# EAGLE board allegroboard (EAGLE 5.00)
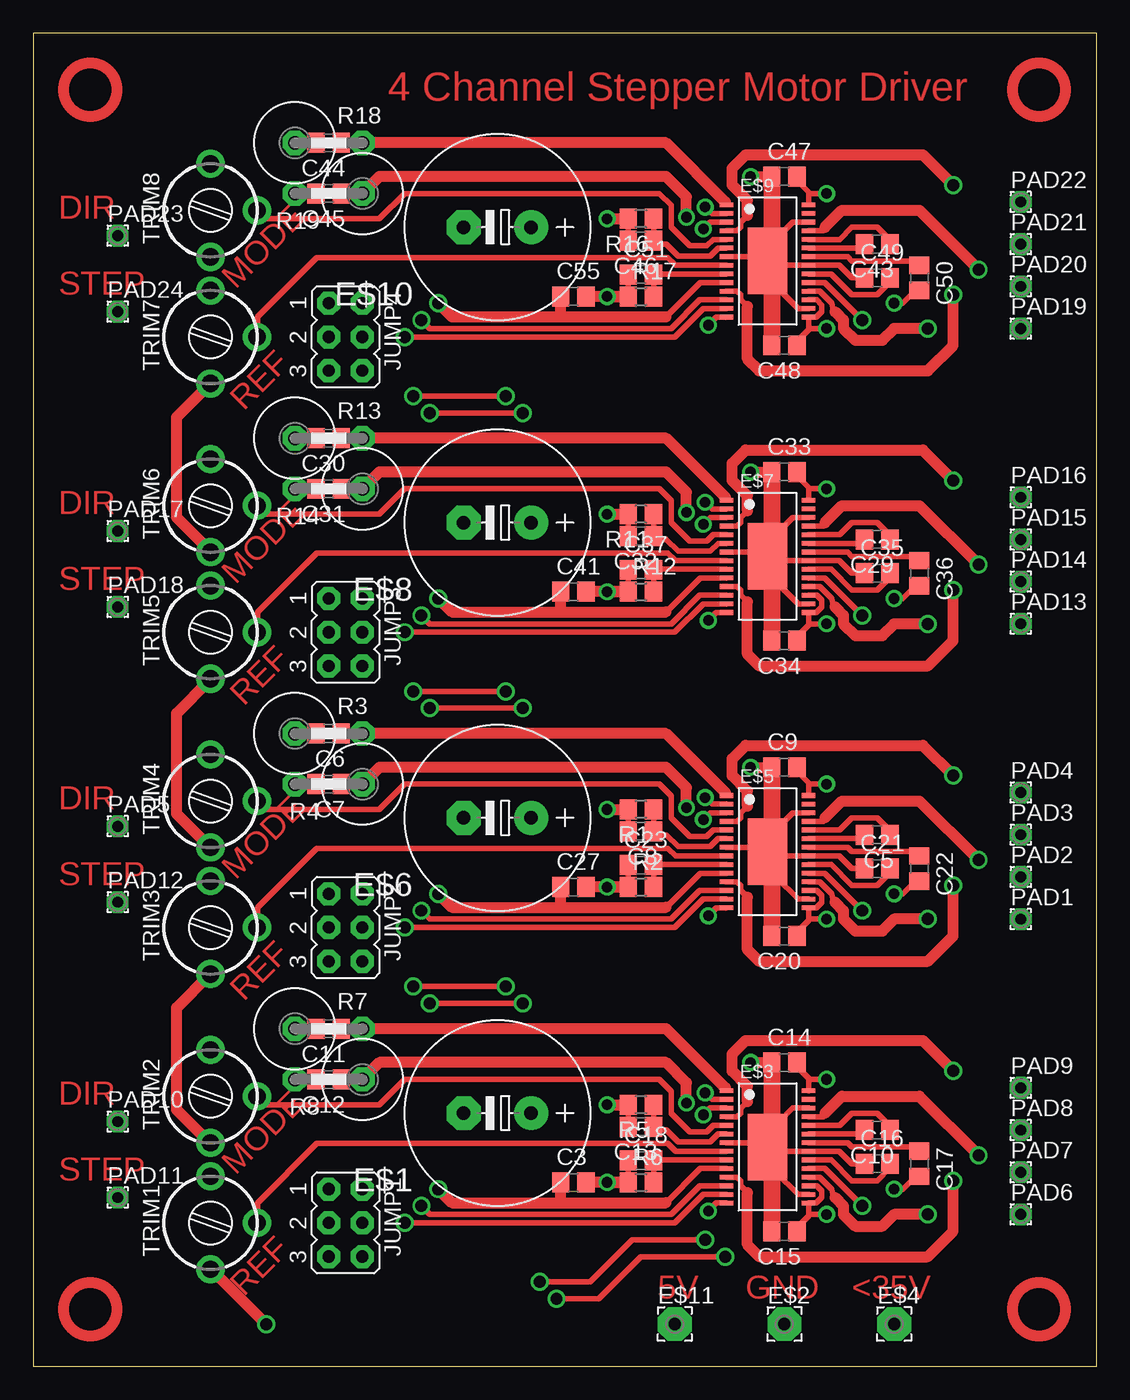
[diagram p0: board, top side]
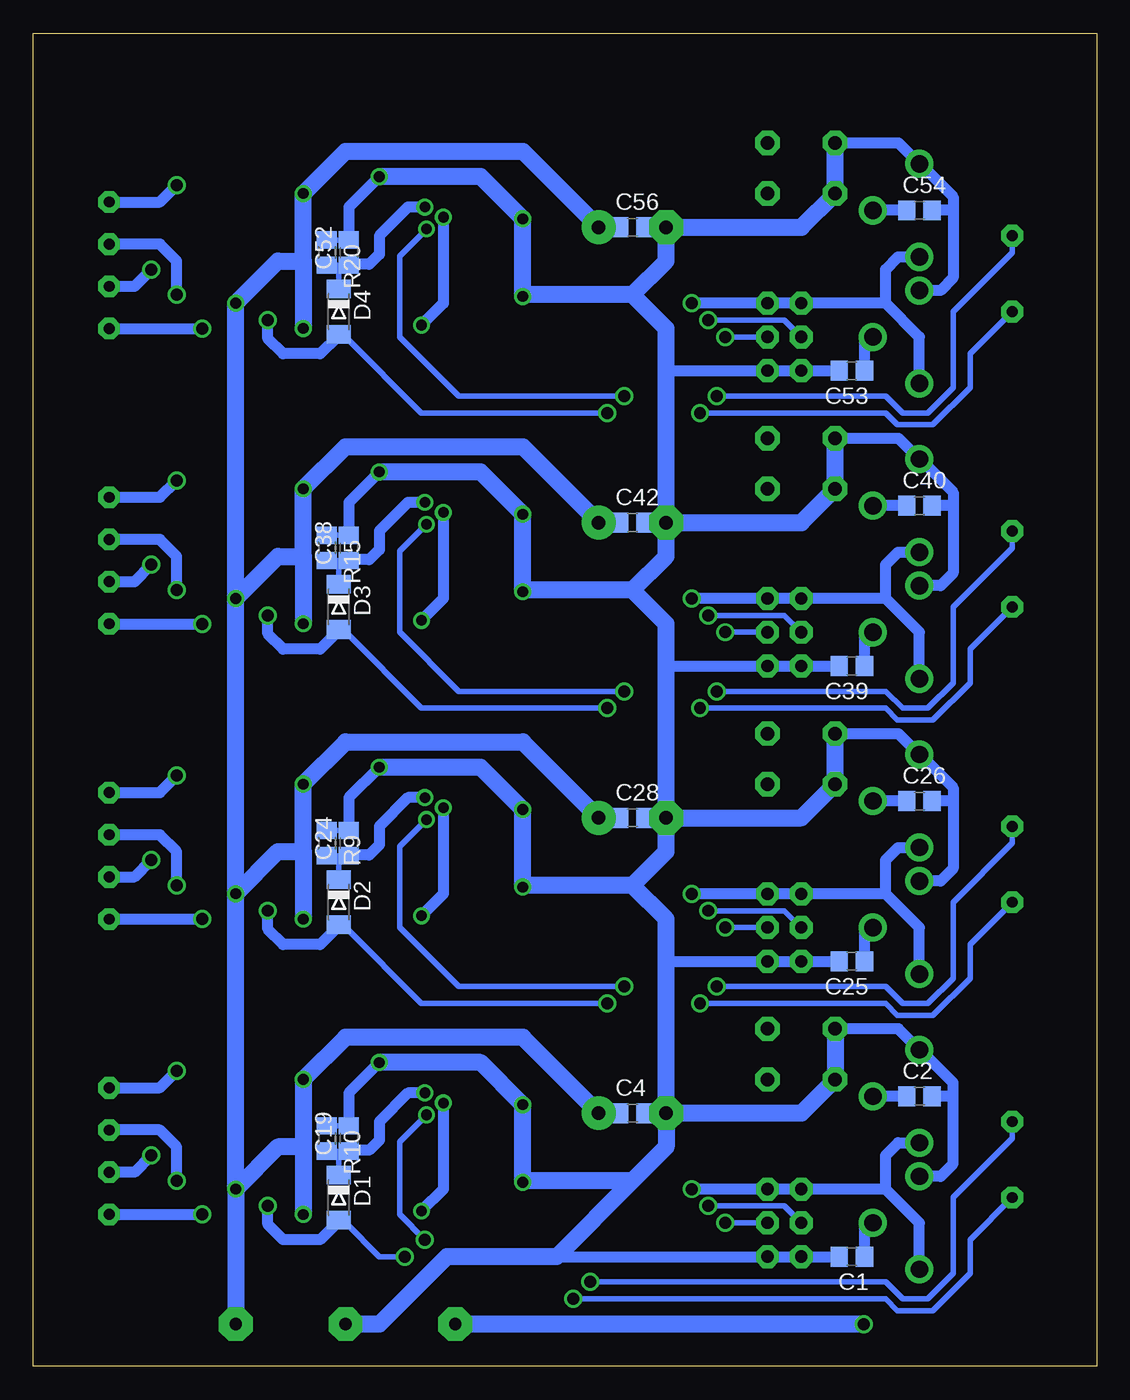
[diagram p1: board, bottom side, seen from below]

Size 80.01 x 100.33 mm. Coordinates in mm from the lower left corner, seen from the top.
Outline: 0,0 80.01,0 80.01,100.33 0,100.33 0,0
Copper layers (1*16): Top 0.035mm / dielectric 1.5mm / Bottom 0.035mm
Design rules "default *": minimum track width 10mil, minimum drill 24mil, track to track 8mil, track to pad 8mil, pad to pad 8mil, via to via 8mil, smd to smd 8mil, copper to edge 40mil, drill to drill 8mil, minimum pad ring 16mil, minimum via ring 8mil, stop-mask expansion 4mil, vias tented up to drill 0mil, thermal gap 10mil

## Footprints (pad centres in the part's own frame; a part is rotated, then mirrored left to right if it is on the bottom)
C0805 = smd 1.3 x 1.5: 1 -0.95,0; 2 0.95,0
MINIMELF = smd 1.4 x 1.8: A 1.7,0; C -1.7,0
E5-13 = drill 1.016 pad 2.54 round: + -2.54,0 | drill 1.016 pad 2.54 octagon: - 2.54,0
2,54/0,9 = drill 0.914 pad 2.54 octagon: 1 0,0
TSSOP28 = smd 0.35 x 1: 1 -4.225,-3.087; 2 -3.575,-3.087; 3 -2.925,-3.087; 4 -2.275,-3.087; 5 -1.625,-3.087; 6 -0.975,-3.087; 7 -0.325,-3.087; 8 0.325,-3.087; 9 0.975,-3.087; 10 1.625,-3.087; 11 2.275,-3.087; 12 2.925,-3.087; 13 3.575,-3.087; 14 4.225,-3.087; 15 4.225,3.087; 16 3.575,3.087; 17 2.925,3.087; 18 2.275,3.087; 19 1.625,3.087; 20 0.975,3.087; 21 0.325,3.087; 22 -0.325,3.087; 23 -0.975,3.087; 24 -1.625,3.087; 25 -2.275,3.087; 26 -2.925,3.087; 27 -3.575,3.087; 28 -4.225,3.087 | smd 5 x 3: EXP 0,0
JP3Q = drill 0.914 octagon: 1 -2.54,-1.27; 2 -2.54,1.27; 3 0,-1.27; 4 0,1.27; 5 2.54,-1.27; 6 2.54,1.27
1,6/0,8 = drill 0.813 pad 1.6 octagon: 1 0,0
R0805 = smd 1.3 x 1.5: 1 -0.95,0; 2 0.95,0
0617V = drill 1.016 octagon: 1 -2.54,0; 2 2.54,0
CTRIM3040.427 = drill 1.3 round: 1A -3.5,0; 1B 3.5,0; 2 0,-3.5

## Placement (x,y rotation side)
C1  100n  [C0805]  18.41,8.26 180 bottom
C2  100n  [C0805]  13.34,20.32 0 bottom
C3  100n  [C0805]  40.64,13.84 0 top
C4  100n  [C0805]  34.92,19.05 0 bottom
C5  220n  [C0805]  63.5,40.01 180 top
C6  100n  [C0805]  22.23,47.62 180 top
C7  100n  [C0805]  22.23,43.81 180 top
C8  1n  [C0805]  45.72,40.26 180 top
C9  100n  [C0805]  56.52,45.09 0 top
C10  220n  [C0805]  63.5,17.78 180 top
C11  100n  [C0805]  22.23,25.4 180 top
C12  100n  [C0805]  22.23,21.59 180 top
C13  1n  [C0805]  45.72,18.03 180 top
C14  100n  [C0805]  56.52,22.86 0 top
C15  100n  [C0805]  56.52,10.16 180 top
C16  220n  [C0805]  63.5,15.24 0 top
C17  220n  [C0805]  66.67,15.24 270 top
C18  1n  [C0805]  45.72,15.49 0 top
C19  100n  [C0805]  56.26,17.14 90 bottom
C20  100n  [C0805]  56.52,32.38 180 top
C21  220n  [C0805]  63.5,37.47 0 top
C22  220n  [C0805]  66.67,37.47 270 top
C23  1n  [C0805]  45.72,37.72 0 top
C24  100n  [C0805]  56.26,39.37 90 bottom
C25  100n  [C0805]  18.41,30.48 180 bottom
C26  100n  [C0805]  13.34,42.55 0 bottom
C27  100n  [C0805]  40.64,36.07 0 top
C28  100n  [C0805]  34.92,41.27 0 bottom
C29  220n  [C0805]  63.5,62.23 180 top
C30  100n  [C0805]  22.23,69.85 180 top
C31  100n  [C0805]  22.23,66.04 180 top
C32  1n  [C0805]  45.72,62.48 180 top
C33  100n  [C0805]  56.52,67.31 0 top
C34  100n  [C0805]  56.52,54.61 180 top
C35  220n  [C0805]  63.5,59.69 0 top
C36  220n  [C0805]  66.67,59.69 270 top
C37  1n  [C0805]  45.72,59.94 0 top
C38  100n  [C0805]  56.26,61.59 90 bottom
C39  100n  [C0805]  18.41,52.7 180 bottom
C40  100n  [C0805]  13.34,64.77 0 bottom
C41  100n  [C0805]  40.64,58.29 0 top
C42  100n  [C0805]  34.92,63.5 0 bottom
C43  220n  [C0805]  63.5,84.45 180 top
C44  100n  [C0805]  22.23,92.08 180 top
C45  100n  [C0805]  22.23,88.27 180 top
C46  1n  [C0805]  45.72,84.71 180 top
C47  100n  [C0805]  56.52,89.53 0 top
C48  100n  [C0805]  56.52,76.83 180 top
C49  220n  [C0805]  63.5,81.92 0 top
C50  220n  [C0805]  66.67,81.92 270 top
C51  1n  [C0805]  45.72,82.17 0 top
C52  100n  [C0805]  56.26,83.82 90 bottom
C53  100n  [C0805]  18.41,74.93 180 bottom
C54  100n  [C0805]  13.34,87 0 bottom
C55  100n  [C0805]  40.64,80.52 0 top
C56  100n  [C0805]  34.92,85.72 0 bottom
D1  [MINIMELF]  57.02,12.7 270 bottom
D2  [MINIMELF]  57.02,34.92 270 bottom
D3  [MINIMELF]  57.02,57.15 270 bottom
D4  [MINIMELF]  57.02,79.38 270 bottom
E$1  470µ  [E5-13]  34.92,19.05 180 top
E$2  [2,54/0,9]  56.52,3.17 0 top
E$3  [TSSOP28]  55.24,16.51 270 top
E$4  [2,54/0,9]  64.77,3.17 0 top
E$5  [TSSOP28]  55.24,38.73 270 top
E$6  470µ  [E5-13]  34.92,41.27 180 top
E$7  [TSSOP28]  55.24,60.96 270 top
E$8  470µ  [E5-13]  34.92,63.5 180 top
E$9  [TSSOP28]  55.24,83.19 270 top
E$10  470µ  [E5-13]  34.92,85.72 180 top
E$11  [2,54/0,9]  48.26,3.17 0 top
JUMP1  [JP3Q]  23.5,10.79 270 top
JUMP2  [JP3Q]  23.5,33.02 270 top
JUMP3  [JP3Q]  23.5,55.24 270 top
JUMP4  [JP3Q]  23.5,77.47 270 top
PAD1  [1,6/0,8]  74.3,33.66 0 top
PAD2  [1,6/0,8]  74.3,36.83 0 top
PAD3  [1,6/0,8]  74.3,40.01 0 top
PAD4  [1,6/0,8]  74.3,43.18 0 top
PAD5  [1,6/0,8]  6.35,40.64 0 top
PAD6  [1,6/0,8]  74.3,11.43 0 top
PAD7  [1,6/0,8]  74.3,14.61 0 top
PAD8  [1,6/0,8]  74.3,17.78 0 top
PAD9  [1,6/0,8]  74.3,20.95 0 top
PAD10  [1,6/0,8]  6.35,18.41 0 top
PAD11  [1,6/0,8]  6.35,12.7 0 top
PAD12  [1,6/0,8]  6.35,34.92 0 top
PAD13  [1,6/0,8]  74.3,55.88 0 top
PAD14  [1,6/0,8]  74.3,59.05 0 top
PAD15  [1,6/0,8]  74.3,62.23 0 top
PAD16  [1,6/0,8]  74.3,65.41 0 top
PAD17  [1,6/0,8]  6.35,62.87 0 top
PAD18  [1,6/0,8]  6.35,57.15 0 top
PAD19  [1,6/0,8]  74.3,78.11 0 top
PAD20  [1,6/0,8]  74.3,81.28 0 top
PAD21  [1,6/0,8]  74.3,84.45 0 top
PAD22  [1,6/0,8]  74.3,87.63 0 top
PAD23  [1,6/0,8]  6.35,85.09 0 top
PAD24  [1,6/0,8]  6.35,79.38 0 top
R1  30k  [R0805]  45.72,41.91 180 top
R2  30k  [R0805]  45.72,36.07 0 top
R3  0,22  [0617V]  22.23,47.62 0 top
R4  0,22  [0617V]  22.23,43.81 180 top
R5  30k  [R0805]  45.72,19.68 180 top
R6  30k  [R0805]  45.72,13.84 0 top
R7  0,22  [0617V]  22.23,25.4 0 top
R8  0,22  [0617V]  22.23,21.59 180 top
R9  10k  [R0805]  57.91,39.37 270 bottom
R10  10k  [R0805]  57.91,17.14 270 bottom
R11  30k  [R0805]  45.72,64.14 180 top
R12  30k  [R0805]  45.72,58.29 0 top
R13  0,22  [0617V]  22.23,69.85 0 top
R14  0,22  [0617V]  22.23,66.04 180 top
R15  10k  [R0805]  57.91,61.59 270 bottom
R16  30k  [R0805]  45.72,86.36 180 top
R17  30k  [R0805]  45.72,80.52 0 top
R18  0,22  [0617V]  22.23,92.08 0 top
R19  0,22  [0617V]  22.23,88.27 180 top
R20  10k  [R0805]  57.91,83.82 270 bottom
TRIM1  [CTRIM3040.427]  13.34,10.79 90 top
TRIM2  [CTRIM3040.427]  13.34,20.32 90 top
TRIM3  [CTRIM3040.427]  13.34,33.02 90 top
TRIM4  [CTRIM3040.427]  13.34,42.55 90 top
TRIM5  [CTRIM3040.427]  13.34,55.24 90 top
TRIM6  [CTRIM3040.427]  13.34,64.77 90 top
TRIM7  [CTRIM3040.427]  13.34,77.47 90 top
TRIM8  [CTRIM3040.427]  13.34,87 90 top

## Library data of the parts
C1-C56 = ref-packages
D1-D4 = diode
E$1 E$6 E$8 E$10 R1-R20 TRIM1-TRIM8 = rcl
E$2 E$4 E$11 PAD1-PAD24 = wirepad
E$3 E$5 E$7 E$9 = linear
JUMP1-JUMP4 = jumper

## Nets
GND1: C1.2 C2.2 C3.2 C4.2 C6.2 C7.2 C8.2 C9.1 C11.2 C12.2 C13.2 C14.1 C15.2 C16.1 C18.1 C19.2 C20.2 C21.1 C23.1 C24.2 C25.2 C26.2 C27.2 C28.2 C30.2 C31.2 C32.2 C33.1 C34.2 C35.1 C37.1 C38.2 C39.2 C40.2 C41.2 C42.2 C44.2 C45.2 C46.2 C47.1 C48.2 C49.1 C51.1 C52.2 C53.2 C54.2 C55.2 C56.2 E$1.- E$2.1 E$3.7 E$3.16 E$3.21 E$3.26 E$3.EXP E$5.7 E$5.16 E$5.21 E$5.26 E$5.EXP E$6.- E$7.7 E$7.16 E$7.21 E$7.26 E$7.EXP E$8.- E$9.7 E$9.16 E$9.21 E$9.26 E$9.EXP E$10.- JUMP1.5 JUMP1.6 JUMP2.5 JUMP2.6 JUMP3.5 JUMP3.6 JUMP4.5 JUMP4.6 R1.2 R2.1 R3.1 R4.2 R5.2 R6.1 R7.1 R8.2 R9.1 R10.1 R11.2 R12.1 R13.1 R14.2 R15.1 R16.2 R17.1 R18.1 R19.2 R20.1 TRIM1.1B TRIM2.1B TRIM3.1B TRIM4.1B TRIM5.1B TRIM6.1B TRIM7.1B TRIM8.1B
S$1: E$3.18 PAD6.1
S$2: C8.1 E$5.6 R1.1
S$3: C23.2 E$5.9 R2.2
S$4: C5.1 E$5.24
S$5: C5.2 E$5.23
S$6: C21.2 E$5.20
S$7: C22.1 E$5.22
S$8: E$5.25 PAD2.1
S$9: E$5.11 PAD3.1
S$10: E$5.4 PAD4.1
S$11: E$5.13 JUMP2.4
S$12: E$5.12 JUMP2.3
S$13: C25.1 E$5.8 TRIM3.2
S$14: C26.1 E$5.5 TRIM4.2
S$15: E$5.3 PAD5.1
S$16: C13.1 E$3.6 R5.1
S$17: C6.1 E$5.1 R3.2
S$18: C3.1 C27.1 C41.1 C55.1 E$3.10 E$5.10 E$7.10 E$9.10 E$11.1 JUMP1.1 JUMP1.2 JUMP2.1 JUMP2.2 JUMP3.1 JUMP3.2 JUMP4.1 JUMP4.2 TRIM1.1A TRIM2.1A TRIM3.1A TRIM4.1A TRIM5.1A TRIM6.1A TRIM7.1A TRIM8.1A
S$19: C18.2 E$3.9 R6.2
S$20: C10.1 E$3.24
S$21: C10.2 E$3.23
S$22: C1.1 E$3.8 TRIM1.2
S$23: C16.2 E$3.20
S$24: C17.1 E$3.22
S$25: E$3.25 PAD7.1
S$27: E$3.11 PAD8.1
S$28: E$3.4 PAD9.1
S$29: E$3.13 JUMP1.4
S$30: E$3.12 JUMP1.3
S$31: C24.1 D2.C E$5.2 R9.2
S$32: E$5.18 PAD1.1
S$33: C2.1 E$3.5 TRIM2.2
S$35: E$3.3 PAD10.1
S$36: D1.A E$3.19 PAD11.1
S$37: D2.A E$5.19 PAD12.1
S$38: C11.1 E$3.1 R7.2
S$39: C4.1 C9.2 C14.2 C15.1 C17.2 C20.1 C22.2 C28.1 C33.2 C34.1 C36.2 C42.1 C47.2 C48.1 C50.2 C56.1 E$1.+ E$3.15 E$3.17 E$3.28 E$4.1 E$5.15 E$5.17 E$5.28 E$6.+ E$7.15 E$7.17 E$7.28 E$8.+ E$9.15 E$9.17 E$9.28 E$10.+
S$40: C19.1 D1.C E$3.2 R10.2
S$41: C32.1 E$7.6 R11.1
S$42: C37.2 E$7.9 R12.2
S$43: C29.1 E$7.24
S$44: C29.2 E$7.23
S$45: C35.2 E$7.20
S$46: C36.1 E$7.22
S$47: E$7.25 PAD14.1
S$48: E$7.11 PAD15.1
S$49: E$7.4 PAD16.1
S$50: E$7.13 JUMP3.4
S$51: E$7.12 JUMP3.3
S$52: C39.1 E$7.8 TRIM5.2
S$53: C40.1 E$7.5 TRIM6.2
S$54: E$7.3 PAD17.1
S$55: C30.1 E$7.1 R13.2
S$57: C38.1 D3.C E$7.2 R15.2
S$58: E$7.18 PAD13.1
S$60: D3.A E$7.19 PAD18.1
S$61: C46.1 E$9.6 R16.1
S$62: C51.2 E$9.9 R17.2
S$63: C43.1 E$9.24
S$64: C43.2 E$9.23
S$65: C49.2 E$9.20
S$66: C50.1 E$9.22
S$67: E$9.25 PAD20.1
S$68: E$9.11 PAD21.1
S$69: E$9.4 PAD22.1
S$70: E$9.13 JUMP4.4
S$71: E$9.12 JUMP4.3
S$72: C53.1 E$9.8 TRIM7.2
S$73: C54.1 E$9.5 TRIM8.2
S$74: E$9.3 PAD23.1
S$75: C44.1 E$9.1 R18.2
S$77: C52.1 D4.C E$9.2 R20.2
S$78: E$9.18 PAD19.1
S$80: D4.A E$9.19 PAD24.1
SENSE1: C12.1 E$3.14 R8.1
SENSE2: C7.1 E$5.14 R4.1
SENSE3: C31.1 E$7.14 R14.1
SENSE4: C45.1 E$9.14 R19.1

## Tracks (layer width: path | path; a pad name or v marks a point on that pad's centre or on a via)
GND1  (via drill 0.8 pad 1.27)
  Top 0.305: E$3.26 58.26,19.43 | E$3.EXP 55.24,17.5 | E$5.26 58.26,41.66 | E$5.EXP 55.24,39.73 | E$7.26 58.26,63.88 | E$7.EXP 55.24,61.95 | E$9.26 58.26,86.11 | E$9.EXP 55.24,84.18
  Top 0.406: 62.57,15.54 62.87,15.24 C16.1 61.59,15.24 60.65,16.18 E$3.21 55.57,16.18 E$3.EXP | E$3.16 57.55,12.94 55.88,14.61 55.56,14.61 | E$3.26 57.15,19.43 56.13,18.41 56.13,17.4 E$3.EXP | E$3.7 54.92,16.84 E$3.EXP | C18.1 44.77,15.55 45.09,15.24 44.77,14.93 R6.1 | C13.2 44.77,18.1 44.83,18.16 44.77,18.22 R5.2 | 62.57,37.76 62.87,37.47 C21.1 61.59,37.47 60.65,38.41 E$5.21 55.57,38.41 E$5.EXP | E$5.16 57.55,35.16 55.88,36.83 55.56,36.83 | E$5.26 57.15,41.66 56.13,40.64 56.13,39.62 E$5.EXP | E$5.7 54.92,39.06 E$5.EXP | C23.1 44.77,37.78 45.09,37.47 44.77,37.15 R2.1 | C8.2 44.77,40.33 44.83,40.39 44.77,40.45 R1.2 | 62.57,59.98 62.87,59.69 C35.1 61.59,59.69 60.65,60.63 E$7.21 55.57,60.63 E$7.EXP | E$7.16 57.55,57.38 55.88,59.05 55.56,59.05 | E$7.26 57.15,63.88 56.13,62.87 56.13,61.85 E$7.EXP | E$7.7 54.92,61.28 E$7.EXP | C37.1 44.77,60.01 45.09,59.69 44.77,59.38 R12.1 | C32.2 44.77,62.55 44.83,62.61 44.77,62.67 R11.2 | 62.57,82.21 62.87,81.92 C49.1 61.59,81.92 60.65,82.86 E$9.21 55.57,82.86 E$9.EXP | E$9.16 57.55,79.61 55.88,81.28 55.56,81.28 | E$9.26 57.15,86.11 56.13,85.09 56.13,84.07 E$9.EXP | E$9.7 54.92,83.51 E$9.EXP | C51.1 44.77,82.23 45.09,81.92 44.77,81.6 R17.1 | C46.2 44.77,84.78 44.83,84.84 44.77,84.9 R16.2
  Top 0.813: 55.56,14.61 55.56,16.19 E$3.EXP 55.56,16.83 | C3.2 41.59,13.9 41.53,13.84 R6.1 v43.18,13.84 | v53.98,22.86 C14.1 | 19.68,25.09 R7.1 C11.2 21.59,25.4 | R8.2 C12.2 | 55.56,36.83 55.56,38.41 E$5.EXP 55.56,39.05 | C27.2 41.59,36.13 41.53,36.07 R2.1 v43.18,36.07 | v53.98,45.09 C9.1 | 19.68,47.31 R3.1 C6.2 21.59,47.62 | R4.2 C7.2 | 55.56,59.05 55.56,60.64 E$7.EXP 55.56,61.28 | C41.2 41.59,58.35 41.53,58.29 R12.1 v43.18,58.29 | v53.98,67.31 C33.1 | 19.68,69.53 R13.1 C30.2 21.59,69.85 | R14.2 C31.2 | 55.56,81.28 55.56,82.86 E$9.EXP 55.56,83.5 | C55.2 41.59,80.58 41.53,80.52 R17.1 v43.18,80.52 | v53.98,89.53 C47.1 | 19.68,91.76 R18.1 C44.2 21.59,92.08 | R19.2 C45.2 | v43.18,19.68 R5.2 v43.18,19.68 | v43.18,41.91 R1.2 v43.18,41.91 | v43.18,64.14 R11.2 v43.18,64.14 | v43.18,86.36 R16.2 v43.18,86.36
  Top 1.27: 55.56,14.61 C15.2 | C14.1 55.56,16.83 | 55.56,36.83 C20.2 | C9.1 55.56,39.05 | 55.56,59.05 C34.2 | C33.1 55.56,61.28 | 55.56,81.28 C48.2 | C47.1 55.56,83.5
  Bottom 0.406: R10.1 57.91,17.91 57.78,17.78 57.47,18.09 C19.2 | R9.1 57.91,40.13 57.78,40.01 57.47,40.32 C24.2 | R15.1 57.91,62.36 57.78,62.23 57.47,62.55 C38.2 | R20.1 57.91,84.58 57.78,84.45 57.47,84.77 C52.2
  Bottom 0.813: C19.2 56.26,20.57 v53.98,22.86 | 43.18,13.97 v43.18,13.84 | C1.2 JUMP1.5 JUMP1.6 40.64,8.26 | TRIM1.1B 11.74,14.29 10.79,15.24 10.79,20.32 | 10.79,20.32 10.79,21.34 13.03,23.57 TRIM2.1B 14.91,25.4 R7.1 | 10.79,20.32 C2.2 | E$1.- C4.2 | C24.2 56.26,42.8 v53.98,45.09 | 43.18,36.2 v43.18,36.07 | C25.2 JUMP2.5 JUMP2.6 32.38,30.48 | TRIM3.1B 11.74,36.52 10.79,37.47 10.79,42.55 | 10.79,42.55 10.79,43.56 13.03,45.79 TRIM4.1B 14.91,47.62 R3.1 | 10.79,42.55 C26.2 | E$6.- C28.2 | C38.2 56.26,65.02 v53.98,67.31 | 43.18,58.42 v43.18,58.29 | C39.2 JUMP3.5 JUMP3.6 32.38,52.7 | TRIM5.1B 11.74,58.74 10.79,59.69 10.79,64.77 | 10.79,64.77 10.79,65.79 13.03,68.02 TRIM6.1B 14.91,69.85 R13.1 | 10.79,64.77 C40.2 | E$8.- C42.2 | C52.2 56.26,87.25 v53.98,89.53 | 43.18,80.64 v43.18,80.52 | C53.2 JUMP4.5 JUMP4.6 32.38,74.93 | TRIM7.1B 11.74,80.97 10.79,81.92 10.79,87 | 10.79,87 10.79,88.01 13.03,90.24 TRIM8.1B 14.91,92.08 R18.1 | 10.79,87 C54.2 | E$10.- C56.2
  Bottom 1.27: v53.98,22.86 46.35,22.86 v43.18,19.68 43.18,13.97 34.92,13.97 | R7.1 R8.2 22.23,19.05 E$1.- | E$1.- 32.38,16.51 34.92,13.97 | v53.98,45.09 46.35,45.09 v43.18,41.91 43.18,36.2 34.92,36.2 | R3.1 R4.2 22.23,41.27 E$6.- | E$6.- 32.38,38.73 34.92,36.2 | v53.98,67.31 46.35,67.31 v43.18,64.14 43.18,58.42 34.92,58.42 | R13.1 R14.2 22.23,63.5 E$8.- | E$8.- 32.38,60.96 34.92,58.42 | v53.98,89.53 46.35,89.53 v43.18,86.36 43.18,80.64 34.92,80.64 | R18.1 R19.2 22.23,85.72 E$10.- 32.38,83.19 34.92,80.64 | E$2.1 53.98,3.17 48.9,8.26 40.64,8.26 34.92,13.97 | E$6.- 32.38,52.7 32.38,55.88 34.92,58.42 | E$8.- 32.38,74.93 32.38,78.11 34.92,80.64 | E$1.- 32.38,30.48 32.38,33.66 34.92,36.2
S$1  (via drill 0.9 pad 0.41)
  Top 0.406: E$3.18 59.17,14.23 60.07,13.34 60.2,12.83 60.33,12.7
  Top 0.813: 60.33,12.7 60.96,12.06 60.96,11.43 61.85,10.54 63.88,10.54 64.77,11.43 v67.31,11.43
  Bottom 0.813: PAD6.1 v67.31,11.43
S$2
  Top 0.406: R1.1 46.67,40.32 46.61,40.26 | C8.1 46.48,40.26 46.35,40.39 46.35,40.01 | 46.35,40.01 46.35,39.75 | 46.61,40.26 46.35,40.01 | C8.1 46.61,40.26 | 46.35,40.01 46.65,39.71 | E$5.6 51.52,39.71 50.93,39.12 48.51,39.12 47.62,40.01 46.99,40.01 46.74,40.26 C8.1
S$3
  Top 0.406: R2.2 46.67,37.4 46.61,37.47 46.67,37.53 C23.2 46.61,37.85 | 46.61,37.85 46.35,38.1 | E$5.9 46.7,37.76 46.61,37.85
S$4
  Top 0.406: E$5.24 60.68,40.36 61.59,41.27 63.5,41.27 64.45,40.33 C5.1
S$5
  Top 0.406: C5.2 62.87,40.01 62.57,39.71 E$5.23
S$6
  Top 0.406: E$5.20 60.03,37.76 61.59,36.2 63.5,36.2 64.45,37.15 C21.2
S$7
  Top 0.406: E$5.22 61.27,39.06 61.59,38.73 66.67,38.73 C22.1
S$8  (via drill 0.9 pad 0.41)
  Top 0.406: E$5.25 59.42,41.01 59.56,41.27
  Top 0.813: 59.56,41.27 60.83,42.55 66.67,42.55 v71.12,38.1
  Bottom 0.813: PAD2.1 72.39,36.83 v71.12,38.1
S$9  (via drill 0.9 pad 0.41)
  Top 0.406: E$5.11 52.95,36.46 53.21,36.2 53.21,35.81 53.72,35.31
  Top 0.813: 53.72,35.31 53.72,31.37 54.61,30.48 67.31,30.48 69.22,32.38 v69.22,36.2
  Bottom 0.813: PAD3.1 70.48,40.01 69.22,38.73 v69.22,36.2
S$10  (via drill 0.9 pad 0.41)
  Top 0.406: E$5.4 52.95,41.01 53.21,41.27 53.21,41.66 53.72,42.16
  Top 0.813: 53.72,42.16 53.72,43.31 52.58,44.45 52.58,45.72 53.59,46.74 66.93,46.74 v69.22,44.45
  Bottom 0.813: PAD4.1 70.48,43.18 v69.22,44.45
S$11  (via drill 0.9 pad 0.41)
  Top 0.406: E$5.13 50.4,35.16 48.26,33.02 v27.94,33.02
  Bottom 0.406: JUMP2.4 v27.94,33.02
S$12  (via drill 0.9 pad 0.41)
  Top 0.406: E$5.12 50.16,35.81 48.01,33.66 29.84,33.66 v29.21,34.29
  Bottom 0.406: JUMP2.3 23.5,34.29 v29.21,34.29
S$13
  Top 0.406: E$5.8 48.33,38.41 47.75,38.99 21.34,38.99 16.89,34.54 16.89,33.4 16.51,33.02 TRIM3.2
  Bottom 0.813: TRIM3.2 17.14,33.02 17.46,32.7 C25.1
S$14
  Top 0.406: 48.64,40.64 48.01,41.27 48.01,42.93 47.12,43.81 27.94,43.81 26.04,41.91 17.4,41.91 16.76,42.55 TRIM4.2 | 48.64,40.64 48.92,40.36 | E$5.5 51.16,40.36 50.67,39.88 49.4,39.88 48.64,40.64
  Bottom 0.813: C26.1 TRIM4.2
S$15  (via drill 0.8 pad 1.27, 0.9 pad 0.41)
  Top 0.406: E$5.3 50.93,41.66 v50.42,41.15 | v28.57,28.57 v35.56,28.57
  Bottom 0.406: v50.42,41.15 52.45,39.12 52.45,33.02 48.01,28.57 v35.56,28.57 | v28.57,28.57 15.88,28.57 14.61,27.3 12.7,27.3 10.79,29.21 10.79,34.92 6.35,39.37 PAD5.1
S$16
  Top 0.406: R5.1 46.67,18.09 46.61,18.03 | C13.1 46.48,18.03 46.35,18.16 46.35,17.78 | 46.35,17.78 46.35,17.53 | 46.61,18.03 46.35,17.78 | C13.1 46.61,18.03 | 46.35,17.78 46.65,17.48 | E$3.6 51.52,17.48 50.93,16.89 48.51,16.89 47.62,17.78 46.99,17.78 46.74,18.03 C13.1
S$17
  Top 0.305: E$5.1 52.16,43.09 52.07,43.18
  Top 0.813: 22.86,47.62 C6.1 R3.2 47.62,47.62 52.07,43.18
S$18  (via drill 0.9 pad 0.41)
  Top 0.406: E$3.10 50.19,14.88 47.62,12.32 | E$5.10 50.19,37.11 47.62,34.54 | E$7.10 50.19,59.34 47.62,56.77 | E$9.10 50.19,81.56 47.62,78.99
  Top 0.813: 39.75,12.32 31.5,12.32 v30.48,13.34 | 39.75,12.32 47.62,12.32 | C3.1 39.69,12.38 39.75,12.32 | 39.75,34.54 31.5,34.54 v30.48,35.56 | 39.75,34.54 47.62,34.54 | C27.1 39.69,34.6 39.75,34.54 | 39.75,56.77 31.5,56.77 v30.48,57.78 | 39.75,56.77 47.62,56.77 | C41.1 39.69,56.83 39.75,56.77 | 39.75,78.99 31.5,78.99 v30.48,80.01 | 39.75,78.99 47.62,78.99 | C55.1 39.69,79.06 39.75,78.99 | TRIM3.1A 10.79,26.98 10.79,19.3 13.34,16.76 TRIM2.1A | TRIM4.1A 10.79,41.59 10.79,49.15 13.34,51.69 TRIM5.1A | TRIM7.1A 10.79,71.43 10.79,63.88 13.34,61.34 TRIM6.1A | TRIM1.1A 13.41,7.29 v17.53,3.17
  Bottom 0.813: TRIM2.1A 14.93,16.82 15.88,15.88 15.88,13.34 | v30.48,13.34 JUMP1.2 JUMP1.1 15.88,13.34 | 15.88,13.34 13.34,10.79 TRIM1.1A | TRIM4.1A 14.93,39.05 15.88,38.1 15.88,35.56 | v30.48,35.56 JUMP2.2 JUMP2.1 15.88,35.56 | 15.88,35.56 13.34,33.02 TRIM3.1A | TRIM6.1A 14.93,61.27 15.88,60.33 15.88,57.78 | v30.48,57.78 JUMP3.2 JUMP3.1 15.88,57.78 | 15.88,57.78 13.34,55.24 TRIM5.1A | TRIM8.1A 14.93,83.5 15.88,82.55 15.88,80.01 | v30.48,80.01 JUMP4.2 JUMP4.1 15.88,80.01 | 15.88,80.01 13.34,77.47 TRIM7.1A
  Bottom 1.27: v17.53,3.17 E$11.1
S$19
  Top 0.406: R6.2 46.67,15.18 46.61,15.24 46.67,15.3 C18.2 46.61,15.62 | 46.61,15.62 46.35,15.88 | E$3.9 46.7,15.54 46.61,15.62
S$20
  Top 0.406: E$3.24 60.68,18.14 61.59,19.05 63.5,19.05 64.45,18.1 C10.1
S$21
  Top 0.406: C10.2 62.87,17.78 62.57,17.48 E$3.23
S$22
  Top 0.406: E$3.8 48.33,16.18 47.75,16.76 21.34,16.76 16.89,12.32 16.89,11.18 16.51,10.79 TRIM1.2
  Bottom 0.813: TRIM1.2 17.14,10.79 17.46,10.47 C1.1
S$23
  Top 0.406: E$3.20 60.03,15.54 61.59,13.97 63.5,13.97 64.45,14.92 C16.2
S$24
  Top 0.406: E$3.22 61.27,16.84 61.59,16.51 66.67,16.51 C17.1
S$25  (via drill 0.9 pad 0.41)
  Top 0.406: E$3.25 59.42,18.79 59.56,19.05
  Top 0.813: 59.56,19.05 60.83,20.32 66.67,20.32 v71.12,15.88
  Bottom 0.813: PAD7.1 72.39,14.61 v71.12,15.88
S$27  (via drill 0.9 pad 0.41)
  Top 0.406: E$3.11 52.95,14.23 53.21,13.97 53.21,13.59 53.72,13.08
  Top 0.813: 53.72,13.08 53.72,9.14 54.61,8.26 67.31,8.26 69.22,10.16 v69.22,13.97
  Bottom 0.813: PAD8.1 70.48,17.78 69.22,16.51 v69.22,13.97
S$28  (via drill 0.9 pad 0.41)
  Top 0.406: E$3.4 52.95,18.79 53.21,19.05 53.21,19.43 53.72,19.94
  Top 0.813: 53.72,19.94 53.72,21.08 52.58,22.23 52.58,23.5 53.59,24.51 66.93,24.51 v69.22,22.23
  Bottom 0.813: PAD9.1 70.48,20.95 v69.22,22.23
S$29  (via drill 0.9 pad 0.41)
  Top 0.406: E$3.13 50.4,12.94 48.26,10.79 v27.94,10.79
  Bottom 0.406: JUMP1.4 v27.94,10.79
S$30  (via drill 0.9 pad 0.41)
  Top 0.406: E$3.12 50.16,13.59 48.01,11.43 29.84,11.43 v29.21,12.06
  Bottom 0.406: JUMP1.3 23.5,12.06 v29.21,12.06
S$31  (via drill 0.8 pad 1.27)
  Top 0.406: E$5.2 51.07,42.31 v50.55,42.8
  Bottom 0.406: R9.2 57.91,38.23 57.78,38.1 57.47,38.42 57.15,38.42 | 57.15,38.42 C24.1 | 57.15,38.42 57.15,38.1 57.02,37.97 D2.C
  Bottom 0.813: v50.55,42.8 51.82,42.8 53.98,40.64 53.98,39.24 54.74,38.48 56.13,38.48 56.26,38.35 C24.1
S$32  (via drill 0.9 pad 0.41)
  Top 0.406: E$5.18 59.17,36.46 60.07,35.56 60.2,35.05 60.33,34.92
  Top 0.813: 60.33,34.92 60.96,34.29 60.96,33.66 61.85,32.77 63.88,32.77 64.77,33.66 v67.31,33.66
  Bottom 0.813: PAD1.1 v67.31,33.66
S$33
  Top 0.406: 48.64,18.41 48.01,19.05 48.01,20.7 47.12,21.59 27.94,21.59 26.04,19.68 17.4,19.68 16.76,20.32 TRIM2.2 | 48.64,18.41 48.92,18.14 | E$3.5 51.16,18.14 50.67,17.65 49.4,17.65 48.64,18.41
  Bottom 0.813: C2.1 TRIM2.2
S$35  (via drill 0.8 pad 1.27, 0.9 pad 0.41)
  Top 0.406: E$3.3 50.93,19.43 v50.42,18.92 | v50.55,9.53 45.09,9.53 41.91,6.35 v38.1,6.35
  Bottom 0.406: v50.42,18.92 52.45,16.89 52.45,11.43 v50.55,9.53 | v38.1,6.35 15.88,6.35 14.61,5.08 12.7,5.08 10.79,6.99 10.79,12.7 6.35,17.14 PAD10.1
S$36  (via drill 0.9, 0.9 pad 0.41)
  Top 0.406: E$3.19 59.54,14.88 v62.36,12.06 | v52.07,8.26 45.72,8.26 42.55,5.08 v39.37,5.08
  Bottom 0.406: 57.15,10.79 56.52,10.79 53.98,8.26 v52.07,8.26 | v39.37,5.08 15.88,5.08 14.99,4.19 12.32,4.19 9.53,6.99 9.53,9.53 PAD11.1
  Bottom 0.813: D1.A 57.02,10.92 57.15,10.79 58.42,9.53 61.21,9.53 62.36,10.67 v62.36,12.06
S$37  (via drill 0.9, 0.9 pad 0.41)
  Top 0.406: E$5.19 59.54,37.11 v62.36,34.29 | v29.84,27.3 v36.83,27.3
  Bottom 0.406: 57.15,33.02 56.52,33.02 50.8,27.3 v36.83,27.3 | v29.84,27.3 15.88,27.3 14.99,26.42 12.32,26.42 9.53,29.21 9.53,31.75 PAD12.1
  Bottom 0.813: D2.A 57.02,33.15 57.15,33.02 58.42,31.75 61.21,31.75 62.36,32.89 v62.36,34.29
S$38
  Top 0.305: E$3.1 52.16,20.87 52.07,20.95
  Top 0.813: 22.86,25.4 C11.1 R7.2 47.62,25.4 52.07,20.95
S$39  (via drill 0.8 pad 1.27)
  Top 0.406: C14.2 57.15,22.86 58.33,21.68 E$3.28 58.33,21.5 58.42,21.59 v59.69,21.59 | C17.2 66.67,14.61 65.41,13.34 v64.77,13.34 | E$3.17 58.93,13.59 59.31,13.21 59.31,12.7 58.89,12.29 E$3.15 58.33,11.43 | v59.69,11.43 58.33,11.43 | 58.33,11.43 58.33,11.34 58.29,11.3 | 58.29,11.3 57.47,10.47 C15.1 57.15,10.16 58.29,11.3 | C9.2 57.15,45.09 58.33,43.9 E$5.28 58.33,43.73 58.42,43.81 v59.69,43.81 | C22.2 66.67,36.83 65.41,35.56 v64.77,35.56 | E$5.17 58.93,35.81 59.31,35.43 59.31,34.92 58.89,34.51 E$5.15 58.33,33.66 | v59.69,33.66 58.33,33.66 | 58.33,33.66 58.33,33.57 58.29,33.53 | 58.29,33.53 57.47,32.7 C20.1 57.15,32.38 58.29,33.53 | C33.2 57.15,67.31 58.33,66.13 E$7.28 58.33,65.95 58.42,66.04 v59.69,66.04 | C36.2 66.67,59.05 65.41,57.78 v64.77,57.78 | E$7.17 58.93,58.03 59.31,57.66 59.31,57.15 58.89,56.73 E$7.15 58.33,55.88 | v59.69,55.88 58.33,55.88 | 58.33,55.88 58.33,55.79 58.29,55.75 | 58.29,55.75 57.47,54.92 C34.1 57.15,54.61 58.29,55.75 | C47.2 57.15,89.53 58.33,88.35 E$9.28 58.33,88.18 58.42,88.27 v59.69,88.27 | C50.2 66.67,81.28 65.41,80.01 v64.77,80.01 | E$9.17 58.93,80.26 59.31,79.88 59.31,79.38 58.89,78.96 E$9.15 58.33,78.11 | v59.69,78.11 58.33,78.11 | 58.33,78.11 58.33,78.02 58.29,77.98 | 58.29,77.98 57.47,77.15 C48.1 57.15,76.83 58.29,77.98
  Bottom 0.813: C4.1 E$1.+ | E$6.+ C28.1 | E$8.+ C42.1 | E$10.+ C56.1
  Bottom 1.27: 59.69,16.51 v59.69,21.59 56.52,24.77 43.18,24.77 E$1.+ | 59.69,16.51 v59.69,11.43 | v64.77,13.34 E$4.1 | 59.69,38.73 v59.69,43.81 56.52,46.99 43.18,46.99 E$6.+ | 59.69,38.73 v59.69,33.66 | v64.77,13.34 v64.77,35.56 | 59.69,60.96 v59.69,66.04 56.52,69.22 43.18,69.22 E$8.+ | 59.69,60.96 v59.69,55.88 | v64.77,35.56 v64.77,57.78 | 59.69,83.19 v59.69,88.27 56.52,91.44 43.18,91.44 E$10.+ | 59.69,83.19 v59.69,78.11 | v64.77,57.78 v64.77,80.01 61.59,83.19 59.69,83.19 | v64.77,57.78 61.59,60.96 59.69,60.96 | v64.77,35.56 61.59,38.73 59.69,38.73 | v64.77,13.34 61.59,16.51 59.69,16.51
S$40  (via drill 0.8 pad 1.27)
  Top 0.406: E$3.2 51.07,20.09 v50.55,20.57
  Bottom 0.406: R10.2 57.91,16 57.78,15.88 57.47,16.2 57.15,16.2 | 57.15,16.2 C19.1 | 57.15,16.2 57.15,15.88 57.02,15.75 D1.C
  Bottom 0.813: v50.55,20.57 51.82,20.57 53.98,18.41 53.98,17.02 54.74,16.26 56.13,16.26 56.26,16.13 C19.1
S$41
  Top 0.406: R11.1 46.67,62.55 46.61,62.48 | C32.1 46.48,62.48 46.35,62.61 46.35,62.23 | 46.35,62.23 46.35,61.98 | 46.61,62.48 46.35,62.23 | C32.1 46.61,62.48 | 46.35,62.23 46.65,61.94 | E$7.6 51.52,61.94 50.93,61.34 48.51,61.34 47.62,62.23 46.99,62.23 46.74,62.48 C32.1
S$42
  Top 0.406: R12.2 46.67,59.63 46.61,59.69 46.67,59.75 C37.2 46.61,60.07 | 46.61,60.07 46.35,60.33 | E$7.9 46.7,59.98 46.61,60.07
S$43
  Top 0.406: E$7.24 60.68,62.59 61.59,63.5 63.5,63.5 64.45,62.55 C29.1
S$44
  Top 0.406: C29.2 62.87,62.23 62.57,61.94 E$7.23
S$45
  Top 0.406: E$7.20 60.03,59.98 61.59,58.42 63.5,58.42 64.45,59.37 C35.2
S$46
  Top 0.406: E$7.22 61.27,61.28 61.59,60.96 66.67,60.96 C36.1
S$47  (via drill 0.9 pad 0.41)
  Top 0.406: E$7.25 59.42,63.23 59.56,63.5
  Top 0.813: 59.56,63.5 60.83,64.77 66.67,64.77 v71.12,60.33
  Bottom 0.813: PAD14.1 72.39,59.05 v71.12,60.33
S$48  (via drill 0.9 pad 0.41)
  Top 0.406: E$7.11 52.95,58.69 53.21,58.42 53.21,58.04 53.72,57.53
  Top 0.813: 53.72,57.53 53.72,53.59 54.61,52.7 67.31,52.7 69.22,54.61 v69.22,58.42
  Bottom 0.813: PAD15.1 70.48,62.23 69.22,60.96 v69.22,58.42
S$49  (via drill 0.9 pad 0.41)
  Top 0.406: E$7.4 52.95,63.23 53.21,63.5 53.21,63.88 53.72,64.39
  Top 0.813: 53.72,64.39 53.72,65.53 52.58,66.67 52.58,67.94 53.59,68.96 66.93,68.96 v69.22,66.67
  Bottom 0.813: PAD16.1 70.48,65.41 v69.22,66.67
S$50  (via drill 0.9 pad 0.41)
  Top 0.406: E$7.13 50.4,57.38 48.26,55.24 v27.94,55.24
  Bottom 0.406: JUMP3.4 v27.94,55.24
S$51  (via drill 0.9 pad 0.41)
  Top 0.406: E$7.12 50.16,58.03 48.01,55.88 29.84,55.88 v29.21,56.52
  Bottom 0.406: JUMP3.3 23.5,56.52 v29.21,56.52
S$52
  Top 0.406: E$7.8 48.33,60.63 47.75,61.21 21.34,61.21 16.89,56.77 16.89,55.63 16.51,55.24 TRIM5.2
  Bottom 0.813: TRIM5.2 17.14,55.24 17.46,54.92 C39.1
S$53
  Top 0.406: 48.64,62.87 48.01,63.5 48.01,65.15 47.12,66.04 27.94,66.04 26.04,64.14 17.4,64.14 16.76,64.77 TRIM6.2 | 48.64,62.87 48.92,62.59 | E$7.5 51.16,62.59 50.67,62.1 49.4,62.1 48.64,62.87
  Bottom 0.813: C40.1 TRIM6.2
S$54  (via drill 0.8 pad 1.27, 0.9 pad 0.41)
  Top 0.406: E$7.3 50.93,63.88 v50.42,63.37 | v35.56,50.8 v28.57,50.8
  Bottom 0.406: v50.42,63.37 52.45,61.34 52.45,55.24 48.01,50.8 v35.56,50.8 | v28.57,50.8 15.88,50.8 14.61,49.53 12.7,49.53 10.79,51.44 10.79,57.15 6.35,61.59 PAD17.1
S$55
  Top 0.305: E$7.1 52.16,65.32 52.07,65.41
  Top 0.813: 22.86,69.85 C30.1 R13.2 47.62,69.85 52.07,65.41
S$57  (via drill 0.8 pad 1.27)
  Top 0.406: E$7.2 51.07,64.53 v50.55,65.02
  Bottom 0.406: R15.2 57.91,60.45 57.78,60.33 57.47,60.65 57.15,60.65 | 57.15,60.65 C38.1 | 57.15,60.65 57.15,60.33 57.02,60.2 D3.C
  Bottom 0.813: v50.55,65.02 51.82,65.02 53.98,62.87 53.98,61.47 54.74,60.71 56.13,60.71 56.26,60.58 C38.1
S$58  (via drill 0.9 pad 0.41)
  Top 0.406: E$7.18 59.17,58.69 60.07,57.78 60.2,57.28 60.33,57.15
  Top 0.813: 60.33,57.15 60.96,56.52 60.96,55.88 61.85,54.99 63.88,54.99 64.77,55.88 v67.31,55.88
  Bottom 0.813: PAD13.1 v67.31,55.88
S$60  (via drill 0.9, 0.9 pad 0.41)
  Top 0.406: E$7.19 59.54,59.34 v62.36,56.52 | v36.83,49.53 v29.84,49.53
  Bottom 0.406: 57.15,55.24 56.52,55.24 50.8,49.53 v36.83,49.53 | v29.84,49.53 15.88,49.53 14.99,48.64 12.32,48.64 9.53,51.44 9.53,53.98 PAD18.1
  Bottom 0.813: D3.A 57.02,55.37 57.15,55.24 58.42,53.98 61.21,53.98 62.36,55.12 v62.36,56.52
S$61
  Top 0.406: R16.1 46.67,84.77 46.61,84.71 | C46.1 46.48,84.71 46.35,84.84 46.35,84.45 | 46.35,84.45 46.35,84.2 | 46.61,84.71 46.35,84.45 | C46.1 46.61,84.71 | 46.35,84.45 46.65,84.16 | E$9.6 51.52,84.16 50.93,83.57 48.51,83.57 47.62,84.45 46.99,84.45 46.74,84.71 C46.1
S$62
  Top 0.406: R17.2 46.67,81.85 46.61,81.92 46.67,81.98 C51.2 46.61,82.3 | 46.61,82.3 46.35,82.55 | E$9.9 46.7,82.21 46.61,82.3
S$63
  Top 0.406: E$9.24 60.68,84.81 61.59,85.72 63.5,85.72 64.45,84.78 C43.1
S$64
  Top 0.406: C43.2 62.87,84.45 62.57,84.16 E$9.23
S$65
  Top 0.406: E$9.20 60.03,82.21 61.59,80.64 63.5,80.64 64.45,81.59 C49.2
S$66
  Top 0.406: E$9.22 61.27,83.51 61.59,83.19 66.67,83.19 C50.1
S$67  (via drill 0.9 pad 0.41)
  Top 0.406: E$9.25 59.42,85.46 59.56,85.72
  Top 0.813: 59.56,85.72 60.83,87 66.67,87 v71.12,82.55
  Bottom 0.813: PAD20.1 72.39,81.28 v71.12,82.55
S$68  (via drill 0.9 pad 0.41)
  Top 0.406: E$9.11 52.95,80.91 53.21,80.64 53.21,80.26 53.72,79.76
  Top 0.813: 53.72,79.76 53.72,75.82 54.61,74.93 67.31,74.93 69.22,76.83 v69.22,80.64
  Bottom 0.813: PAD21.1 70.48,84.45 69.22,83.19 v69.22,80.64
S$69  (via drill 0.9 pad 0.41)
  Top 0.406: E$9.4 52.95,85.46 53.21,85.72 53.21,86.11 53.72,86.61
  Top 0.813: 53.72,86.61 53.72,87.76 52.58,88.9 52.58,90.17 53.59,91.19 66.93,91.19 v69.22,88.9
  Bottom 0.813: PAD22.1 70.48,87.63 v69.22,88.9
S$70  (via drill 0.9 pad 0.41)
  Top 0.406: E$9.13 50.4,79.61 48.26,77.47 v27.94,77.47
  Bottom 0.406: JUMP4.4 v27.94,77.47
S$71  (via drill 0.9 pad 0.41)
  Top 0.406: E$9.12 50.16,80.26 48.01,78.11 29.84,78.11 v29.21,78.74
  Bottom 0.406: JUMP4.3 23.5,78.74 v29.21,78.74
S$72
  Top 0.406: E$9.8 48.33,82.86 47.75,83.44 21.34,83.44 16.89,78.99 16.89,77.85 16.51,77.47 TRIM7.2
  Bottom 0.813: TRIM7.2 17.14,77.47 17.46,77.15 C53.1
S$73
  Top 0.406: 48.64,85.09 48.01,85.72 48.01,87.38 47.12,88.27 27.94,88.27 26.04,86.36 17.4,86.36 16.76,87 TRIM8.2 | 48.64,85.09 48.92,84.81 | E$9.5 51.16,84.81 50.67,84.33 49.4,84.33 48.64,85.09
  Bottom 0.813: C54.1 TRIM8.2
S$74  (via drill 0.8 pad 1.27, 0.9 pad 0.41)
  Top 0.406: E$9.3 50.93,86.11 v50.42,85.6 | v35.56,73.03 v28.57,73.03
  Bottom 0.406: v50.42,85.6 52.45,83.57 52.45,77.47 48.01,73.03 v35.56,73.03 | v28.57,73.03 15.88,73.03 14.61,71.75 12.7,71.75 10.79,73.66 10.79,79.38 6.35,83.82 PAD23.1
S$75
  Top 0.305: E$9.1 52.16,87.54 52.07,87.63
  Top 0.813: 22.86,92.08 C44.1 R18.2 47.62,92.08 52.07,87.63
S$77  (via drill 0.8 pad 1.27)
  Top 0.406: E$9.2 51.07,86.76 v50.55,87.25
  Bottom 0.406: R20.2 57.91,82.68 57.78,82.55 57.47,82.87 57.15,82.87 | 57.15,82.87 C52.1 | 57.15,82.87 57.15,82.55 57.02,82.42 D4.C
  Bottom 0.813: v50.55,87.25 51.82,87.25 53.98,85.09 53.98,83.69 54.74,82.93 56.13,82.93 56.26,82.8 C52.1
S$78  (via drill 0.9 pad 0.41)
  Top 0.406: E$9.18 59.17,80.91 60.07,80.01 60.2,79.5 60.33,79.38
  Top 0.813: 60.33,79.38 60.96,78.74 60.96,78.11 61.85,77.22 63.88,77.22 64.77,78.11 v67.31,78.11
  Bottom 0.813: PAD19.1 v67.31,78.11
S$80  (via drill 0.9, 0.9 pad 0.41)
  Top 0.406: E$9.19 59.54,81.56 v62.36,78.74 | v36.83,71.75 v29.84,71.75
  Bottom 0.406: 57.15,77.47 56.52,77.47 50.8,71.75 v36.83,71.75 | v29.84,71.75 15.88,71.75 14.99,70.87 12.32,70.87 9.53,73.66 9.53,76.2 PAD24.1
  Bottom 0.813: D4.A 57.02,77.6 57.15,77.47 58.42,76.2 61.21,76.2 62.36,77.34 v62.36,78.74
SENSE1  (via drill 0.8 pad 1.27)
  Top 0: 52.07,12.06 52.16,12.15 E$3.14
  Top 0.406: E$3.14 51.4,12.29 v50.8,11.68
  Top 0.813: C12.1 R8.1 26.04,22.86 47.62,22.86 49.15,21.34 v49.15,19.81
  Bottom 0.813: v49.15,19.81 49.15,13.34 v50.8,11.68
SENSE2  (via drill 0.8 pad 1.27)
  Top 0: 52.07,34.29 52.16,34.38 E$5.14
  Top 0.406: E$5.14 51.4,34.51 v50.8,33.91
  Top 0.813: C7.1 R4.1 26.04,45.09 47.62,45.09 49.15,43.56 v49.15,42.04
  Bottom 0.813: v49.15,42.04 49.15,35.56 v50.8,33.91
SENSE3  (via drill 0.8 pad 1.27)
  Top 0: 52.07,56.52 52.16,56.6 E$7.14
  Top 0.406: E$7.14 51.4,56.73 v50.8,56.13
  Top 0.813: C31.1 R14.1 26.04,67.31 47.62,67.31 49.15,65.79 v49.15,64.26
  Bottom 0.813: v49.15,64.26 49.15,57.78 v50.8,56.13
SENSE4  (via drill 0.8 pad 1.27)
  Top 0: 52.07,78.74 52.16,78.83 E$9.14
  Top 0.406: E$9.14 51.4,78.96 v50.8,78.36
  Top 0.813: C45.1 R19.1 26.04,89.53 47.62,89.53 49.15,88.01 v49.15,86.49
  Bottom 0.813: v49.15,86.49 49.15,80.01 v50.8,78.36
(copper drawn outside any net)
  shapes: Top circle x4

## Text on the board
Top: 4 Channel Stepper Motor Driver | DIR | STEP | MODE | REF | DIR | MODE | STEP | REF | DIR | MODE | STEP | REF | DIR | STEP | MODE | REF | 5V | GND | <35V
